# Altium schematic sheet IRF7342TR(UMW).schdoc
size 127 x 101 mm
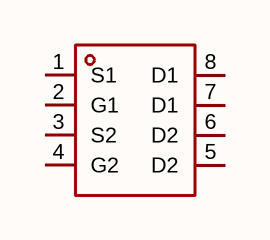
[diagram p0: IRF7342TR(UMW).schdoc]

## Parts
Q?  irf7342tr(umw)  [SOP-8_L4.9-W3.9-P1.27-LS6.0-BL]  (value not drawn)

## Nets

Not connected (* = marked no-connect by the designer): Q? 1(S1) 2(G1) 3(S2) 4(G2) 5(D2) 6(D2) 7(D1) 8(D1)

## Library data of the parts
Q? = irf7342tr(umw): 数量:2个P沟道;漏源电压(Vdss):55V;连续漏极电流(Id):3.4A;导通电阻(RDS(on)):95mΩ@10V；150mΩ@4.5V;耗散功率(Pd):2W;阈值电压(Vgs(th)):1V;; Manufacturer: UMW(友台半导体); AddInBom: yes; ModelId: 75c24a7891ee4dd6bdac16a7163ff87e; ModelName: SOP-8_L4.9-W3.9-P1.27-LS6.0-BL-1; ModelTransform: 192.913,236.22,0,0,0,0,-0.393,2.749,0; Number: 2个P沟道; Drain to Source Voltage: 55V; Current - Continuous Drain(Id): 3.4A; Pd - Power Dissipation: 2W; Gate Threshold Voltage (Vgs(th)): 1V; Gate Charge(Qg): 26nC; Input Capacitance(Ciss): 690pF; Reverse Transfer Capacitance (Crss@Vds): 86pF; Type: P沟道; Output Capacitance(Coss): 210pF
